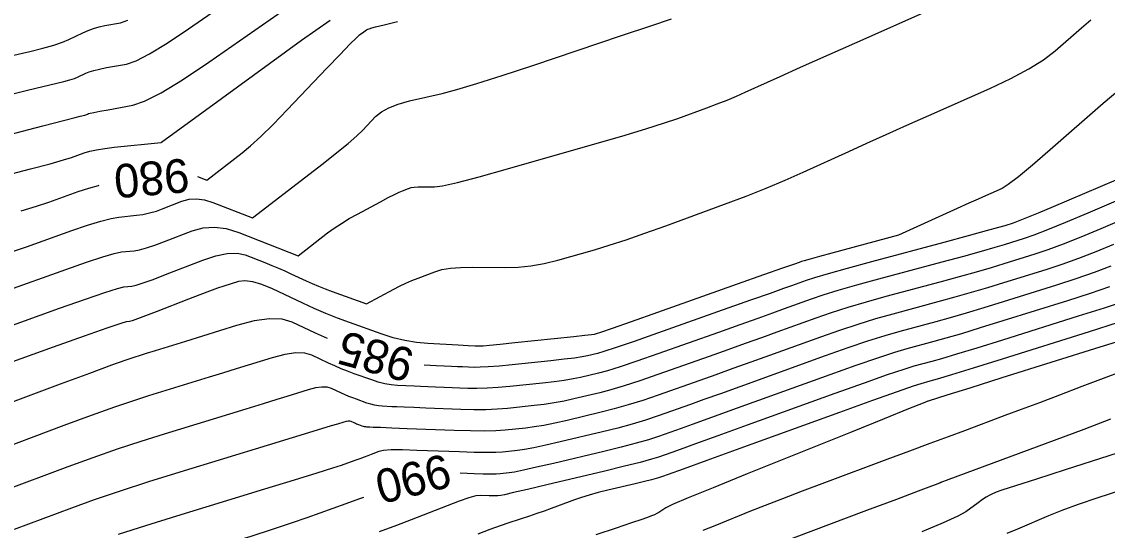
# Model space of a CAD drawing. Extents: x 2175772 to 2185556, y 721391 to 722853.
# Drawn here: x 2178632.3 to 2178722.5, y 721795.3 to 721837.5 of the extents above; entities that cross this region are included whole.
import ezdxf

# ---------------------------------------------------------------- set-up
doc = ezdxf.new("R2010")
doc.units = 0
doc.layers.add('DT_X_Contour_Major', color=7, linetype='Continuous')
doc.layers.add('DT_X_Contour_Minor', color=7, linetype='Continuous')

msp = doc.modelspace()

# ---------------------------------------------------------------- linework, layer by layer
at = {"layer": 'DT_X_Contour_Major'}
for points in [[(2178646.877, 721824.672), (2178647.652, 721824.37), (2178650.587, 721826.637), (2178651.292, 721827.224), (2178652.149, 721828.015), (2178653.158, 721829.009), (2178654.32, 721830.207), (2178657.62, 721833.672), (2178658.719, 721834.82), (2178659.54, 721835.667), (2178660.084, 721836.213), (2178660.35, 721836.456), (2178660.69, 721836.704), (2178660.813, 721836.789), (2178660.928, 721836.858), (2178661.033, 721836.912), (2178661.129, 721836.949), (2178661.374, 721837.028), (2178661.672, 721837.108), (2178662.38, 721837.287), (2178663.499, 721837.566)], [(2178724.501, 721824.937), (2178718.004, 721822.167), (2178716.752, 721821.637), (2178715.78, 721821.234), (2178715.09, 721820.959), (2178714.68, 721820.811), (2178713.961, 721820.586), (2178713.443, 721820.437), (2178712.429, 721820.156), (2178710.918, 721819.746), (2178708.911, 721819.205), (2178702.898, 721817.589), (2178700.868, 721817.038), (2178699.287, 721816.597), (2178698.156, 721816.266), (2178697.474, 721816.046), (2178696.255, 721815.605), (2178695.581, 721815.364), (2178694.473, 721814.97), (2178692.932, 721814.425), (2178690.957, 721813.727), (2178685.113, 721811.663), (2178683.157, 721810.977), (2178681.671, 721810.465), (2178680.654, 721810.129), (2178680.107, 721809.967), (2178679.276, 721809.77), (2178678.853, 721809.69), (2178678.207, 721809.597), (2178677.338, 721809.491), (2178676.245, 721809.373), (2178673.034, 721809.041), (2178671.935, 721808.933), (2178671.044, 721808.861), (2178670.361, 721808.823), (2178669.887, 721808.82), (2178668.902, 721808.857), (2178668.487, 721808.875), (2178667.982, 721808.897), (2178667.387, 721808.926), (2178666.702, 721808.961), (2178665.723, 721809.011)], [(2178632.226, 721821.822), (2178633.5, 721822.209), (2178634.53, 721822.554), (2178636.951, 721823.42), (2178637.831, 721823.712), (2178638.657, 721823.941), (2178638.701, 721823.951)], [(2178722.68, 721815.508), (2178721.057, 721814.959), (2178719.173, 721814.356), (2178713.803, 721812.676), (2178711.935, 721812.096), (2178710.359, 721811.617), (2178709.076, 721811.239), (2178708.084, 721810.961), (2178705.83, 721810.355), (2178704.796, 721810.051), (2178703.387, 721809.59), (2178701.603, 721808.975), (2178699.442, 721808.204), (2178691.037, 721805.168), (2178689.303, 721804.543), (2178687.98, 721804.069), (2178687.066, 721803.744), (2178685.177, 721803.077), (2178684.361, 721802.811), (2178683.332, 721802.516), (2178682.089, 721802.19), (2178680.632, 721801.834), (2178676.461, 721800.845), (2178675.057, 721800.516), (2178673.975, 721800.274), (2178673.215, 721800.116), (2178672.775, 721800.045), (2178672.033, 721799.968), (2178671.689, 721799.946), (2178671.215, 721799.94), (2178670.611, 721799.948), (2178669.876, 721799.972), (2178668.71, 721800.016)], [(2178657.679, 721811.22), (2178657.427, 721811.328), (2178656.691, 721811.665), (2178654.743, 721812.587), (2178653.905, 721812.828), (2178652.853, 721812.859), (2178651.586, 721812.68), (2178650.105, 721812.292), (2178645.87, 721810.976), (2178644.448, 721810.534), (2178643.36, 721810.197), (2178642.604, 721809.963), (2178642.18, 721809.832), (2178641.496, 721809.623), (2178640.926, 721809.426), (2178639.731, 721808.992), (2178637.91, 721808.321), (2178635.464, 721807.413), (2178628.106, 721804.676)], [(2178722.766, 721804.504), (2178720.53, 721803.669), (2178709.111, 721799.407), (2178708.782, 721799.299), (2178708.719, 721799.278), (2178708.672, 721799.261), (2178708.641, 721799.249), (2178708.625, 721799.241), (2178708.604, 721799.225), (2178708.589, 721799.217), (2178708.559, 721799.204), (2178708.514, 721799.186), (2178708.455, 721799.163), (2178708.278, 721799.095), (2178707.866, 721798.939), (2178706.761, 721798.524), (2178704.964, 721797.848), (2178702.475, 721796.913), (2178694.915, 721794.072)], [(2178660.661, 721798.004), (2178660.335, 721797.884), (2178659.194, 721797.473), (2178655.973, 721796.321), (2178654.649, 721795.861), (2178653.092, 721795.346), (2178651.302, 721794.775), (2178649.279, 721794.149), (2178643.573, 721792.406), (2178641.558, 721791.781), (2178639.793, 721791.214), (2178638.279, 721790.704), (2178637.014, 721790.251), (2178633.975, 721789.121), (2178632.542, 721788.572), (2178630.52, 721787.772)]]:
    msp.add_lwpolyline(points, dxfattribs=at)
at = {"layer": 'DT_X_Contour_Minor'}
for points in [[(2178630.806, 721815.129), (2178635.921, 721816.957), (2178637.649, 721817.562), (2178638.995, 721818.005), (2178639.961, 721818.288), (2178640.547, 721818.408), (2178641.6, 721818.515), (2178642.054, 721818.593), (2178642.627, 721818.745), (2178643.318, 721818.972), (2178644.127, 721819.274), (2178646.443, 721820.178), (2178647.335, 721820.423), (2178648.276, 721820.48), (2178649.264, 721820.348), (2178650.299, 721820.029), (2178655.244, 721818.1), (2178657.688, 721819.987), (2178658.236, 721820.389), (2178658.832, 721820.786), (2178659.476, 721821.177), (2178660.169, 721821.564), (2178662.08, 721822.586), (2178662.732, 721822.931), (2178663.252, 721823.198), (2178663.642, 721823.388), (2178663.9, 721823.5), (2178664.415, 721823.696), (2178664.632, 721823.76), (2178664.895, 721823.804), (2178665.206, 721823.828), (2178665.563, 721823.833), (2178666.579, 721823.82), (2178667.243, 721823.91), (2178668.476, 721824.191), (2178670.276, 721824.661), (2178672.643, 721825.322), (2178679.714, 721827.339), (2178682.146, 721828.041), (2178684.138, 721828.637), (2178685.692, 721829.126), (2178686.807, 721829.508), (2178689.193, 721830.385), (2178690.064, 721830.712), (2178690.886, 721831.037), (2178691.659, 721831.359), (2178692.384, 721831.679), (2178694.252, 721832.528), (2178695.289, 721832.995), (2178696.999, 721833.76), (2178699.383, 721834.824), (2178702.441, 721836.185), (2178711.493, 721840.214)], [(2178631.52, 721831.555), (2178632.633, 721831.833), (2178633.438, 721832.025), (2178635.173, 721832.423), (2178635.771, 721832.568), (2178636.267, 721832.705), (2178636.659, 721832.833), (2178636.948, 721832.954), (2178637.581, 721833.264), (2178637.867, 721833.38), (2178638.25, 721833.495), (2178638.731, 721833.61), (2178639.309, 721833.724), (2178640.981, 721834.028), (2178641.772, 721834.296), (2178642.893, 721834.872), (2178644.343, 721835.757), (2178646.123, 721836.949), (2178651.308, 721840.539)], [(2178624.911, 721826.516), (2178634.029, 721828.896), (2178636.71, 721829.592), (2178637.127, 721829.698), (2178637.521, 721829.79), (2178637.605, 721829.813), (2178637.671, 721829.835), (2178637.719, 721829.855), (2178637.826, 721829.907), (2178637.958, 721829.942), (2178638.271, 721830.007), (2178638.768, 721830.102), (2178639.447, 721830.227), (2178641.5, 721830.6), (2178642.473, 721830.929), (2178643.85, 721831.637), (2178645.632, 721832.724), (2178647.819, 721834.189), (2178654.19, 721838.6)], [(2178628.944, 721811.417), (2178635.406, 721813.726), (2178637.557, 721814.487), (2178639.165, 721815.038), (2178640.228, 721815.378), (2178640.748, 721815.508), (2178641.409, 721815.576), (2178641.771, 721815.654), (2178642.36, 721815.839), (2178643.177, 721816.131), (2178644.221, 721816.53), (2178647.308, 721817.735), (2178648.397, 721818.101), (2178649.348, 721818.294), (2178650.162, 721818.316), (2178650.838, 721818.165), (2178652.457, 721817.533), (2178653.049, 721817.297), (2178653.607, 721817.064), (2178654.134, 721816.834), (2178654.628, 721816.606), (2178655.904, 721816.003), (2178656.398, 721815.778), (2178656.925, 721815.555), (2178657.484, 721815.334), (2178658.075, 721815.116), (2178660.91, 721814.102), (2178663.184, 721815.319), (2178663.676, 721815.572), (2178664.177, 721815.81), (2178664.687, 721816.032), (2178665.206, 721816.239), (2178666.602, 721816.77), (2178667.189, 721816.943), (2178667.904, 721817.062), (2178668.746, 721817.129), (2178669.715, 721817.142), (2178672.47, 721817.106), (2178673.517, 721817.135), (2178674.591, 721817.249), (2178675.692, 721817.447), (2178676.82, 721817.731), (2178679.864, 721818.599), (2178681.091, 721818.967), (2178682.491, 721819.423), (2178684.062, 721819.965), (2178685.805, 721820.593), (2178690.683, 721822.384), (2178692.463, 721823.053), (2178694.143, 721823.717), (2178695.723, 721824.376), (2178697.204, 721825.029), (2178701.021, 721826.764), (2178702.511, 721827.439), (2178704.115, 721828.161), (2178705.835, 721828.932), (2178707.669, 721829.75), (2178712.716, 721831.996), (2178714.475, 721832.823), (2178715.966, 721833.62), (2178717.19, 721834.386), (2178718.146, 721835.122), (2178720.34, 721837.044), (2178721.112, 721837.692)], [(2178629.748, 721834.351), (2178632.925, 721835.08), (2178634.022, 721835.346), (2178634.93, 721835.597), (2178635.648, 721835.832), (2178636.177, 721836.053), (2178637.336, 721836.621), (2178637.776, 721836.818), (2178638.229, 721836.984), (2178638.694, 721837.119), (2178639.172, 721837.222), (2178640.461, 721837.457), (2178641.071, 721837.663)], [(2178630.899, 721824.756), (2178633, 721825.309), (2178634.616, 721825.745), (2178635.747, 721826.065), (2178636.392, 721826.267), (2178637.466, 721826.651), (2178637.922, 721826.787), (2178638.487, 721826.909), (2178639.161, 721827.016), (2178639.943, 721827.108), (2178643.848, 721827.507), (2178643.856, 721827.505), (2178643.876, 721827.522), (2178643.886, 721827.532), (2178648.873, 721831.166), (2178655.511, 721836.001), (2178657.914, 721837.66)], [(2178631.254, 721818.354), (2178632.668, 721818.842), (2178636.436, 721820.188), (2178637.74, 721820.637), (2178638.826, 721820.973), (2178639.695, 721821.197), (2178640.345, 721821.308), (2178641.791, 721821.455), (2178642.337, 721821.532), (2178642.893, 721821.651), (2178643.458, 721821.813), (2178644.033, 721822.018), (2178645.578, 721822.621), (2178646.173, 721822.784), (2178646.8, 721822.822), (2178647.459, 721822.735), (2178648.15, 721822.521), (2178651.448, 721821.235), (2178657.309, 721825.762), (2178658.457, 721826.663), (2178659.391, 721827.426), (2178660.111, 721828.051), (2178660.617, 721828.538), (2178661.679, 721829.654), (2178662.154, 721830.049), (2178662.783, 721830.399), (2178663.565, 721830.702), (2178664.501, 721830.96), (2178667.201, 721831.588), (2178668.432, 721831.909), (2178670.101, 721832.404), (2178672.208, 721833.071), (2178674.752, 721833.912), (2178682.119, 721836.384), (2178684.54, 721837.194), (2178686.275, 721837.772)], [(2178723.709, 721832.06), (2178722.158, 721830.76), (2178717.754, 721826.9), (2178716.265, 721825.614), (2178715.101, 721824.651), (2178714.263, 721824.011), (2178713.75, 721823.694), (2178712.817, 721823.278), (2178712.379, 721823.082), (2178711.768, 721822.807), (2178710.983, 721822.451), (2178710.024, 721822.015), (2178705.141, 721819.796), (2178699.609, 721818.309), (2178698.562, 721818.026), (2178697.792, 721817.816), (2178697.298, 721817.679), (2178697.08, 721817.614), (2178696.869, 721817.538), (2178696.489, 721817.403), (2178695.507, 721817.056), (2178693.922, 721816.496), (2178691.735, 721815.724), (2178685.101, 721813.38), (2178682.916, 721812.61), (2178681.338, 721812.055), (2178680.367, 721811.717), (2178680.003, 721811.594), (2178679.84, 721811.555), (2178679.612, 721811.525), (2178679.053, 721811.462), (2178678.162, 721811.366), (2178673.235, 721810.855), (2178672.019, 721810.729), (2178671.148, 721810.639), (2178670.624, 721810.586), (2178670.446, 721810.568), (2178670.431, 721810.568), (2178670.309, 721810.575), (2178669.952, 721810.593), (2178669.361, 721810.623), (2178668.536, 721810.665), (2178666.024, 721810.794), (2178665.075, 721810.88), (2178664.113, 721811.044), (2178663.138, 721811.284), (2178662.15, 721811.602), (2178659.496, 721812.55), (2178658.508, 721812.917), (2178657.533, 721813.307), (2178656.57, 721813.719), (2178655.621, 721814.154), (2178653.107, 721815.344), (2178652.224, 721815.716), (2178651.461, 721815.941), (2178650.818, 721816.018), (2178650.295, 721815.948), (2178649.059, 721815.564), (2178648.527, 721815.389), (2178647.86, 721815.151), (2178647.057, 721814.852), (2178646.118, 721814.49), (2178643.434, 721813.442), (2178642.541, 721813.097), (2178641.874, 721812.848), (2178641.433, 721812.694), (2178641.219, 721812.636), (2178640.95, 721812.608), (2178640.495, 721812.469), (2178639.334, 721812.07), (2178637.466, 721811.412), (2178634.891, 721810.495), (2178627.082, 721807.704)], [(2178726.3, 721823.95), (2178720.88, 721821.64), (2178719.024, 721820.857), (2178717.522, 721820.243), (2178716.374, 721819.798), (2178715.578, 721819.52), (2178713.929, 721819.004), (2178713.141, 721818.768), (2178712.015, 721818.449), (2178710.55, 721818.045), (2178708.746, 721817.556), (2178703.485, 721816.142), (2178701.654, 721815.64), (2178700.107, 721815.195), (2178698.845, 721814.808), (2178697.868, 721814.477), (2178695.64, 721813.672), (2178694.672, 721813.325), (2178693.439, 721812.885), (2178691.941, 721812.354), (2178690.179, 721811.73), (2178685.126, 721809.946), (2178683.398, 721809.344), (2178682.003, 721808.875), (2178680.941, 721808.541), (2178680.212, 721808.341), (2178678.713, 721807.985), (2178678.094, 721807.855), (2178677.361, 721807.732), (2178676.513, 721807.616), (2178675.551, 721807.507), (2178672.834, 721807.226), (2178671.851, 721807.137), (2178670.939, 721807.082), (2178670.098, 721807.06), (2178669.329, 721807.071), (2178667.372, 721807.147), (2178666.665, 721807.175), (2178666.012, 721807.202), (2178665.413, 721807.229), (2178664.868, 721807.256), (2178663.486, 721807.327), (2178662.964, 721807.374), (2178662.434, 721807.464), (2178661.898, 721807.597), (2178661.354, 721807.771), (2178659.894, 721808.293), (2178659.35, 721808.495), (2178658.813, 721808.71), (2178658.284, 721808.937), (2178657.761, 721809.176), (2178656.378, 721809.83), (2178655.783, 721810.001), (2178655.036, 721810.023), (2178654.137, 721809.897), (2178653.086, 721809.621), (2178650.08, 721808.687), (2178648.958, 721808.339), (2178647.85, 721807.997), (2178646.754, 721807.66), (2178645.671, 721807.328), (2178642.799, 721806.451), (2178641.552, 721806.05), (2178639.965, 721805.504), (2178638.039, 721804.815), (2178635.774, 721803.981), (2178629.28, 721801.565)], [(2178726.661, 721822.351), (2178721.947, 721820.341), (2178720.279, 721819.644), (2178718.812, 721819.06), (2178717.544, 721818.588), (2178716.477, 721818.229), (2178713.897, 721817.422), (2178712.84, 721817.1), (2178711.601, 721816.741), (2178710.181, 721816.343), (2178708.581, 721815.908), (2178704.071, 721814.695), (2178702.439, 721814.243), (2178700.927, 721813.794), (2178699.535, 721813.35), (2178698.261, 721812.909), (2178695.025, 721811.74), (2178693.763, 721811.285), (2178692.405, 721810.8), (2178690.951, 721810.282), (2178689.401, 721809.734), (2178685.139, 721808.229), (2178683.639, 721807.711), (2178682.335, 721807.285), (2178681.228, 721806.953), (2178680.317, 721806.714), (2178678.15, 721806.2), (2178677.335, 721806.021), (2178676.514, 721805.868), (2178675.688, 721805.741), (2178674.857, 721805.642), (2178672.634, 721805.411), (2178671.767, 721805.341), (2178670.834, 721805.303), (2178669.835, 721805.297), (2178668.77, 721805.323), (2178665.843, 721805.436), (2178664.844, 721805.475), (2178664.043, 721805.507), (2178663.439, 721805.532), (2178663.034, 721805.551), (2178662.216, 721805.593), (2178661.908, 721805.621), (2178661.595, 721805.675), (2178661.277, 721805.753), (2178660.956, 721805.856), (2178660.092, 721806.165), (2178659.771, 721806.284), (2178659.453, 721806.411), (2178659.14, 721806.545), (2178658.831, 721806.687), (2178658.014, 721807.074), (2178657.662, 721807.175), (2178657.22, 721807.188), (2178656.688, 721807.113), (2178656.067, 721806.95), (2178654.289, 721806.397), (2178653.468, 721806.144), (2178652.34, 721805.797), (2178650.904, 721805.357), (2178644.101, 721803.279), (2178642.177, 721802.673), (2178640.2, 721802.016), (2178638.169, 721801.308), (2178636.084, 721800.548), (2178630.454, 721798.454)], [(2178723.014, 721819.043), (2178721.534, 721818.431), (2178720.101, 721817.876), (2178718.715, 721817.378), (2178717.376, 721816.938), (2178713.866, 721815.84), (2178712.538, 721815.432), (2178711.187, 721815.033), (2178709.813, 721814.642), (2178708.415, 721814.259), (2178704.657, 721813.249), (2178703.225, 721812.845), (2178701.747, 721812.393), (2178700.224, 721811.891), (2178698.655, 721811.341), (2178694.41, 721809.807), (2178692.854, 721809.246), (2178691.371, 721808.714), (2178689.961, 721808.211), (2178688.623, 721807.737), (2178685.151, 721806.511), (2178683.88, 721806.077), (2178682.667, 721805.696), (2178681.515, 721805.366), (2178680.422, 721805.087), (2178677.587, 721804.415), (2178676.576, 721804.186), (2178675.668, 721804.003), (2178674.864, 721803.866), (2178674.163, 721803.776), (2178672.433, 721803.597), (2178671.683, 721803.545), (2178670.729, 721803.524), (2178669.572, 721803.534), (2178668.212, 721803.575), (2178664.313, 721803.725), (2178663.022, 721803.775), (2178662.073, 721803.812), (2178661.465, 721803.836), (2178661.2, 721803.847), (2178660.947, 721803.86), (2178660.852, 721803.869), (2178660.755, 721803.885), (2178660.657, 721803.909), (2178660.558, 721803.941), (2178660.291, 721804.036), (2178660.192, 721804.073), (2178660.094, 721804.112), (2178659.997, 721804.154), (2178659.902, 721804.198), (2178659.649, 721804.317), (2178659.54, 721804.348), (2178659.404, 721804.352), (2178659.24, 721804.329), (2178659.048, 721804.279), (2178658.498, 721804.108), (2178657.978, 721803.949), (2178656.831, 721803.597), (2178652.651, 721802.32), (2178645.404, 721800.106), (2178642.803, 721799.297), (2178640.434, 721798.529), (2178638.298, 721797.802), (2178636.394, 721797.116), (2178631.627, 721795.343)], [(2178722.789, 721817.217), (2178721.391, 721816.692), (2178719.886, 721816.168), (2178718.274, 721815.647), (2178713.834, 721814.258), (2178712.236, 721813.764), (2178710.773, 721813.325), (2178709.444, 721812.94), (2178708.25, 721812.61), (2178705.243, 721811.802), (2178704.011, 721811.448), (2178702.567, 721810.992), (2178700.913, 721810.433), (2178699.049, 721809.772), (2178691.945, 721807.207), (2178690.337, 721806.629), (2178688.97, 721806.14), (2178687.844, 721805.741), (2178685.164, 721804.794), (2178684.12, 721804.444), (2178683, 721804.106), (2178681.802, 721803.778), (2178680.527, 721803.461), (2178677.024, 721802.63), (2178675.816, 721802.351), (2178674.822, 721802.138), (2178674.039, 721801.991), (2178673.469, 721801.91), (2178672.233, 721801.782), (2178671.661, 721801.747), (2178670.872, 721801.736), (2178669.866, 721801.75), (2178668.644, 721801.789), (2178665.095, 721801.925), (2178663.9, 721801.958), (2178662.977, 721801.954), (2178662.327, 721801.914), (2178661.948, 721801.838), (2178661.302, 721801.584), (2178661.036, 721801.482), (2178660.724, 721801.365), (2178660.364, 721801.233), (2178659.958, 721801.087), (2178658.811, 721800.676), (2178658.091, 721800.437), (2178656.792, 721800.026), (2178654.913, 721799.444), (2178652.455, 721798.69), (2178645.127, 721796.451), (2178642.54, 721795.649), (2178640.273, 721794.92)], [(2178723.97, 721814.324), (2178722.227, 721813.749), (2178720.072, 721813.065), (2178713.771, 721811.094), (2178711.633, 721810.428), (2178709.945, 721809.91), (2178708.707, 721809.538), (2178707.919, 721809.313), (2178706.416, 721808.909), (2178705.582, 721808.653), (2178704.207, 721808.189), (2178702.292, 721807.517), (2178699.836, 721806.636), (2178692.565, 721804.009), (2178690.128, 721803.128), (2178688.269, 721802.458), (2178686.989, 721801.998), (2178686.288, 721801.747), (2178685.189, 721801.359), (2178684.602, 721801.178), (2178683.664, 721800.926), (2178682.376, 721800.602), (2178680.736, 721800.207), (2178675.898, 721799.059), (2178674.298, 721798.682), (2178673.129, 721798.409), (2178672.39, 721798.241), (2178672.081, 721798.179), (2178671.832, 721798.153), (2178671.717, 721798.146), (2178671.558, 721798.144), (2178671.355, 721798.147), (2178671.109, 721798.155), (2178670.393, 721798.182), (2178670.019, 721798.136), (2178669.431, 721797.978), (2178668.632, 721797.708), (2178667.62, 721797.326), (2178664.637, 721796.157), (2178663.41, 721795.684), (2178661.967, 721795.144)], [(2178723.398, 721812.539), (2178720.97, 721811.774), (2178713.74, 721809.512), (2178711.332, 721808.76), (2178709.531, 721808.202), (2178708.339, 721807.836), (2178707.753, 721807.664), (2178707.002, 721807.462), (2178706.368, 721807.256), (2178705.027, 721806.788), (2178702.981, 721806.058), (2178700.229, 721805.067), (2178691.95, 721802.076), (2178689.219, 721801.089), (2178687.235, 721800.373), (2178685.999, 721799.927), (2178685.51, 721799.751), (2178685.202, 721799.642), (2178684.994, 721799.581), (2178684.602, 721799.48), (2178684.025, 721799.338), (2178683.263, 721799.155), (2178680.985, 721798.615), (2178680.172, 721798.413), (2178679.439, 721798.212), (2178678.786, 721798.012), (2178678.215, 721797.813), (2178676.799, 721797.285), (2178676.255, 721797.085), (2178675.683, 721796.882), (2178675.085, 721796.674), (2178674.46, 721796.464), (2178672.756, 721795.896), (2178672.042, 721795.649), (2178671.176, 721795.334), (2178670.16, 721794.95)], [(2178724.574, 721811.331), (2178721.879, 721810.486), (2178713.731, 721807.937), (2178711.057, 721807.1), (2178709.146, 721806.503), (2178707.613, 721806.023), (2178707.604, 721806.019), (2178707.601, 721806.018), (2178707.598, 721806.017), (2178707.596, 721806.016), (2178707.591, 721806.015), (2178707.59, 721806.014), (2178707.588, 721806.013), (2178707.586, 721806.013), (2178707.585, 721806.012), (2178707.176, 721805.848), (2178705.968, 721805.362), (2178703.956, 721804.552), (2178701.141, 721803.419), (2178692.562, 721799.966), (2178689.727, 721798.82), (2178687.656, 721797.969), (2178686.349, 721797.415), (2178685.807, 721797.157), (2178685.378, 721796.863), (2178685.214, 721796.758), (2178685.045, 721796.664), (2178684.869, 721796.579), (2178684.688, 721796.506), (2178684.198, 721796.323), (2178683.796, 721796.182), (2178682.958, 721795.899), (2178681.683, 721795.471), (2178679.972, 721794.901)], [(2178725.547, 721809.167), (2178720.383, 721807.218), (2178718.531, 721806.519), (2178716.846, 721805.886), (2178715.33, 721805.317), (2178713.982, 721804.812), (2178710.61, 721803.554), (2178709.26, 721803.05), (2178707.738, 721802.482), (2178706.044, 721801.85), (2178704.179, 721801.154), (2178698.976, 721799.213), (2178697.13, 721798.52), (2178695.492, 721797.896), (2178694.063, 721797.343), (2178692.843, 721796.859), (2178689.867, 721795.661), (2178688.881, 721795.262)], [(2178726.243, 721802.62), (2178719.001, 721800.306), (2178716.606, 721799.539), (2178714.851, 721798.972), (2178713.736, 721798.606), (2178713.262, 721798.441), (2178712.85, 721798.267), (2178712.666, 721798.175), (2178712.425, 721798.028), (2178712.124, 721797.827), (2178711.766, 721797.571), (2178710.732, 721796.816), (2178710.068, 721796.443), (2178708.852, 721795.892), (2178707.085, 721795.163)], [(2178723.588, 721798.582), (2178721.703, 721797.967), (2178720.078, 721797.411), (2178718.715, 721796.914), (2178717.613, 721796.476), (2178715.024, 721795.386), (2178714.142, 721795.004)]]:
    msp.add_lwpolyline(points, dxfattribs=at)

# ---------------------------------------------------------------- texts
at = {"layer": 'DT_X_Contour_Major'}
for s, rotation, p in [('980', 185.04236, (2178646.053, 721826.196)), ('985', 164.64229, (2178665.072, 721810.238)), ('990', 194.03971, (2178667.495, 721801.674))]:
    msp.add_text(s, height=2.8, rotation=rotation, dxfattribs=at).set_placement(p)

doc.saveas('drawing.dxf')
